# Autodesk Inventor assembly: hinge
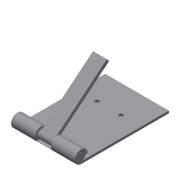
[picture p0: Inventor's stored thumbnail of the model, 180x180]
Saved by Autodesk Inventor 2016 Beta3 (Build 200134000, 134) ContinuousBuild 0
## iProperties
Created: 2016-03
Part Number: hinge
Document SubType Name: Assembly
Designer: Gaurav
Author: Gaurav
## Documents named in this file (3)
- D:\My Data\Books_Final Books\Autodesk Inventor 2015_resources\Chapter 7\Hinge\hinge.iam
- D:\My Data\Books_Final Books\Autodesk Inventor 2015_resources\Chapter 7\Hinge\base.ipt
- D:\My Data\Books_Final Books\Autodesk Inventor 2015_resources\Chapter 7\Hinge\movable_plate.ipt
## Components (2 placed, 2 different names)
1. base:1 — Mate:1, Insert:1
2. movable_plate:1 — Insert:1
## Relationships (2: Mate 1, Insert 1)
- Mate:1: base:1
- Insert:1: base:1 ↔ movable_plate:1
